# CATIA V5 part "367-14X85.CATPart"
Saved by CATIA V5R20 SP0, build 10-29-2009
Part number: 367-14X85
Definition: NONE
Nomenclature: 367-14X85
Source: Unknown
Description: 367-14X85
Bounding box of the stored display mesh (mm): x 0 to 85, y -14 to 14, z -14 to 14
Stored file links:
  C:\Users\Utente\Desktop\IO LAVORO\3D X SITO CF\X SITO\PLASTICA\3D files 367\367-14X85.CATPart
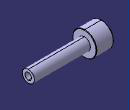
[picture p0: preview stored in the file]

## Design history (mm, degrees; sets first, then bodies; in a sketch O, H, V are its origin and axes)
Body1 "367-14X85" (main body)
  Solid1: solid without history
